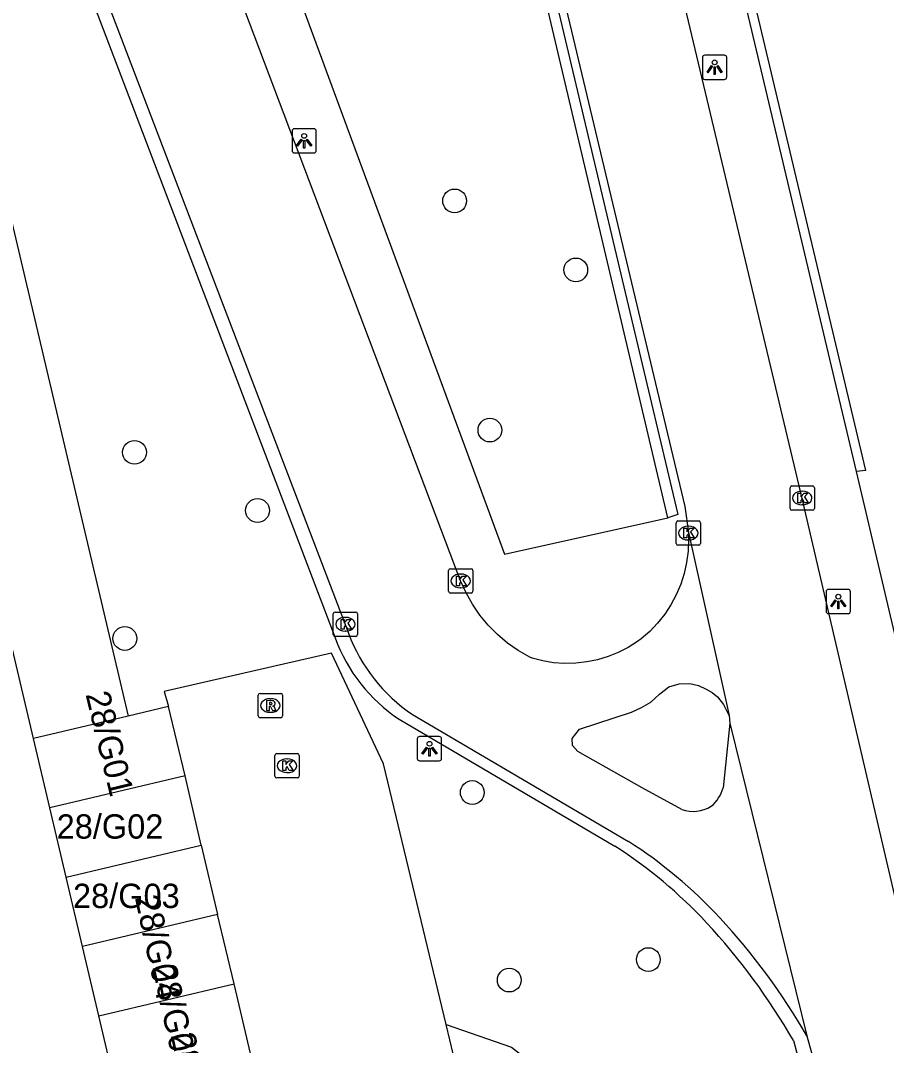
# Model space of a CAD drawing. Extents: x 158038 to 159242, y 380133 to 381214.
# Drawn here: x 158656.77 to 158692.37, y 380931.84 to 380973.99 of the extents above; entities that cross this region are included whole.
import ezdxf

# ---------------------------------------------------------------- set-up
doc = ezdxf.new("R2010")
doc.units = 0
for name, color, linetype in [('IMGEO_Boom', 7, 'Continuous'), ('IMGEO_Fietspad_open', 7, 'Continuous'), ('IMGEO_Groenvoorziening', 7, 'Continuous'), ('IMGEO_Kolk', 7, 'Continuous'), ('IMGEO_Lichtpunt', 7, 'Continuous'), ('IMGEO_Muur', 7, 'Continuous'), ('IMGEO_Pand', 7, 'Continuous'), ('IMGEO_Pand_nummerreeks', 7, 'Continuous'), ('IMGEO_Rijbaan_lokaal_open', 7, 'Continuous'), ('IMGEO_Rioolput', 7, 'Continuous'), ('IMGEO_Voetpad_open', 7, 'Continuous')]:
    doc.layers.add(name, color=color, linetype=linetype)

msp = doc.modelspace()

# ---------------------------------------------------------------- linework, layer by layer
at = {"layer": 'IMGEO_Boom'}
for centre in [(158674.616, 380966.569), (158679.594, 380963.733), (158676.065, 380957.145), (158661.456, 380956.231), (158666.512, 380953.838), (158661.059, 380948.576), (158675.342, 380942.239), (158682.578, 380935.369), (158676.862, 380934.526)]:
    msp.add_circle(centre, 0.489, dxfattribs=at)
at = {"layer": 'IMGEO_Fietspad_open'}
for points in [[(158709.619, 380866.64), (158709.463, 380867.521), (158707.319, 380876.312), (158699.376, 380909.991), (158693.603, 380934.169), (158688.921, 380954.272), (158678.032, 381000), (158677.125, 381004.39), (158673.033, 381021.228), (158672.927, 381021.669), (158667.035, 381046.28), (158663.617, 381061.042), (158663.576, 381061.221), (158663, 381063.616), (158656.793, 381089.506)], [(158672.361, 381001.891), (158674.016, 380996.666), (158679.129, 380974.762), (158684.079, 380953.998), (158684.223, 380952.937)], [(158652.006, 380996.675), (158660.379, 380974.663), (158670.252, 380948.792)], [(158684.223, 380952.937), (158684.233, 380952.634), (158684.213, 380952.167), (158684.152, 380951.704), (158684.049, 380951.249), (158683.907, 380950.804), (158683.725, 380950.374), (158683.505, 380949.962), (158683.25, 380949.572), (158682.961, 380949.205), (158682.64, 380948.866), (158682.29, 380948.557), (158682.134, 380948.445), (158681.749, 380948.204), (158681.344, 380947.999), (158680.922, 380947.831), (158680.487, 380947.701), (158680.043, 380947.61), (158679.591, 380947.56), (158679.138, 380947.55), (158678.685, 380947.58), (158678.236, 380947.651), (158677.796, 380947.762), (158677.702, 380947.81), (158677.233, 380948.079), (158676.791, 380948.389), (158676.379, 380948.738), (158675.999, 380949.122), (158675.655, 380949.538), (158675.349, 380949.983), (158675.084, 380950.454), (158674.863, 380950.947), (158665.761, 380975.033)], [(158684.223, 380952.937), (158685.897, 380945.401)], [(158683.953, 380941.54), (158682.328, 380942.428), (158679.675, 380943.932), (158679.46, 380944.173), (158679.44, 380944.458), (158679.75, 380944.851), (158681.884, 380945.55), (158682.291, 380945.731), (158682.676, 380945.956), (158683.036, 380946.283), (158683.42, 380946.582), (158683.846, 380946.711), (158684.29, 380946.727), (158684.636, 380946.643), (158684.959, 380946.494), (158685.202, 380946.352), (158685.418, 380946.171), (158685.664, 380945.862), (158685.84, 380945.508), (158685.897, 380945.401)], [(158672.883, 380945.448), (158681.756, 380940.231)], [(158685.897, 380945.401), (158685.924, 380945.089)], [(158685.924, 380945.089), (158685.65, 380942.439)], [(158685.924, 380945.089), (158689.094, 380932.233)], [(158689.094, 380932.233), (158689.866, 380929.463)]]:
    msp.add_lwpolyline(points, dxfattribs=at)
for centre, radius, start, end in [((158676.756, 380951.203), 6.937, 200.3348, 236.0552), ((158684.238, 380942.798), 1.457, 309.4682, 345.7445), ((158684.418, 380942.882), 1.42, 250.869, 301.6659), ((158671.318, 380923.935), 19.352, 42.7931, 57.3595), ((158666.009, 380918.956), 26.63, 29.9054, 42.8947)]:
    msp.add_arc(centre, radius, start, end, dxfattribs=at)
at = {"layer": 'IMGEO_Groenvoorziening'}
for points in [[(158649.276, 380995.98), (158661.198, 380945.385)], [(158657.305, 380944.468), (158645.377, 380995.088)], [(158674.266, 380932.695), (158676.956, 380931.767), (158679.919, 380929.472), (158680.934, 380926.931)]]:
    msp.add_lwpolyline(points, dxfattribs=at)
at = {"layer": 'IMGEO_Kolk'}
for p, q in [((158688.403, 380953.923), (158688.403, 380954.775)), ((158688.478, 380954.849), (158689.33, 380954.849)), ((158688.891, 380954.629), (158688.916, 380954.629)), ((158689.404, 380954.775), (158689.404, 380953.923)), ((158689.33, 380953.849), (158688.478, 380953.849)), ((158688.914, 380954.069), (158688.889, 380954.069)), ((158683.722, 380952.482), (158683.722, 380953.334)), ((158683.797, 380953.408), (158684.649, 380953.408)), ((158684.723, 380953.334), (158684.723, 380952.482)), ((158684.21, 380953.188), (158684.235, 380953.188)), ((158684.233, 380952.628), (158684.208, 380952.628)), ((158684.649, 380952.408), (158683.797, 380952.408)), ((158674.365, 380950.518), (158674.365, 380951.37)), ((158674.44, 380951.444), (158675.292, 380951.444)), ((158674.853, 380951.224), (158674.878, 380951.224)), ((158675.366, 380951.37), (158675.366, 380950.518)), ((158675.292, 380950.444), (158674.44, 380950.444)), ((158674.876, 380950.664), (158674.851, 380950.664)), ((158669.627, 380948.736), (158669.627, 380949.588)), ((158669.702, 380949.662), (158670.554, 380949.662)), ((158670.628, 380949.588), (158670.628, 380948.736)), ((158670.115, 380949.442), (158670.14, 380949.442)), ((158670.554, 380948.662), (158669.702, 380948.662)), ((158670.138, 380948.882), (158670.113, 380948.882)), ((158667.227, 380942.915), (158667.227, 380943.767)), ((158667.302, 380943.841), (158668.154, 380943.841)), ((158667.715, 380943.621), (158667.74, 380943.621)), ((158668.228, 380943.767), (158668.228, 380942.915)), ((158668.154, 380942.841), (158667.302, 380942.841)), ((158667.738, 380943.061), (158667.713, 380943.061))]:
    msp.add_line(p, q, dxfattribs=at)
for points in [[(158688.403, 380953.923), (158688.403, 380954.775)], [(158688.478, 380954.849), (158689.33, 380954.849)], [(158688.724, 380954.549), (158688.847, 380954.549), (158688.847, 380954.398), (158688.977, 380954.549), (158689.141, 380954.549), (158688.995, 380954.398), (158689.148, 380954.149), (158688.996, 380954.149), (158688.911, 380954.313), (158688.847, 380954.246), (158688.847, 380954.149), (158688.724, 380954.149), (158688.724, 380954.549)], [(158689.404, 380954.775), (158689.404, 380953.923)], [(158689.33, 380953.849), (158688.478, 380953.849)], [(158683.722, 380952.482), (158683.722, 380953.334)], [(158683.797, 380953.408), (158684.649, 380953.408)], [(158684.723, 380953.334), (158684.723, 380952.482)], [(158684.043, 380953.108), (158684.166, 380953.108), (158684.166, 380952.957), (158684.296, 380953.108), (158684.46, 380953.108), (158684.314, 380952.957), (158684.467, 380952.708), (158684.315, 380952.708), (158684.23, 380952.872), (158684.166, 380952.805), (158684.166, 380952.708), (158684.043, 380952.708), (158684.043, 380953.108)], [(158684.649, 380952.408), (158683.797, 380952.408)], [(158674.365, 380950.518), (158674.365, 380951.37)], [(158674.44, 380951.444), (158675.292, 380951.444)], [(158675.366, 380951.37), (158675.366, 380950.518)], [(158674.686, 380951.144), (158674.809, 380951.144), (158674.809, 380950.993), (158674.939, 380951.144), (158675.103, 380951.144), (158674.957, 380950.993), (158675.11, 380950.744), (158674.958, 380950.744), (158674.873, 380950.908), (158674.809, 380950.841), (158674.809, 380950.744), (158674.686, 380950.744), (158674.686, 380951.144)], [(158675.292, 380950.444), (158674.44, 380950.444)], [(158669.627, 380948.736), (158669.627, 380949.588)], [(158669.702, 380949.662), (158670.554, 380949.662)], [(158670.628, 380949.588), (158670.628, 380948.736)], [(158669.948, 380949.362), (158670.071, 380949.362), (158670.071, 380949.211), (158670.201, 380949.362), (158670.365, 380949.362), (158670.219, 380949.211), (158670.372, 380948.962), (158670.22, 380948.962), (158670.135, 380949.126), (158670.071, 380949.059), (158670.071, 380948.962), (158669.948, 380948.962), (158669.948, 380949.362)], [(158670.554, 380948.662), (158669.702, 380948.662)], [(158667.227, 380942.915), (158667.227, 380943.767)], [(158667.302, 380943.841), (158668.154, 380943.841)], [(158668.228, 380943.767), (158668.228, 380942.915)], [(158667.548, 380943.541), (158667.671, 380943.541), (158667.671, 380943.39), (158667.801, 380943.541), (158667.965, 380943.541), (158667.819, 380943.39), (158667.972, 380943.141), (158667.82, 380943.141), (158667.735, 380943.305), (158667.671, 380943.238), (158667.671, 380943.141), (158667.548, 380943.141), (158667.548, 380943.541)], [(158668.154, 380942.841), (158667.302, 380942.841)]]:
    msp.add_lwpolyline(points, dxfattribs=at)
for centre, start, end in [((158688.48, 380954.773), 91.552, 178.448), ((158688.48, 380954.773), 91.552, 178.448), ((158689.328, 380954.773), 1.552, 88.448), ((158689.328, 380954.773), 1.552, 88.448), ((158688.48, 380953.925), 181.552, 268.448), ((158688.48, 380953.925), 181.552, 268.448), ((158689.328, 380953.925), 271.552, 358.448), ((158689.328, 380953.925), 271.552, 358.448), ((158683.799, 380953.332), 91.552, 178.448), ((158683.799, 380953.332), 91.552, 178.448), ((158684.647, 380953.332), 1.552, 88.448), ((158684.647, 380953.332), 1.552, 88.448), ((158683.799, 380952.484), 181.552, 268.448), ((158683.799, 380952.484), 181.552, 268.448), ((158684.647, 380952.484), 271.552, 358.448), ((158684.647, 380952.484), 271.552, 358.448), ((158674.442, 380951.368), 91.552, 178.448), ((158674.442, 380951.368), 91.552, 178.448), ((158675.29, 380951.368), 1.552, 88.448), ((158675.29, 380951.368), 1.552, 88.448), ((158674.442, 380950.52), 181.552, 268.448), ((158674.442, 380950.52), 181.552, 268.448), ((158675.29, 380950.52), 271.552, 358.448), ((158675.29, 380950.52), 271.552, 358.448), ((158669.704, 380949.586), 91.552, 178.448), ((158669.704, 380949.586), 91.552, 178.448), ((158670.552, 380949.586), 1.552, 88.448), ((158670.552, 380949.586), 1.552, 88.448), ((158669.704, 380948.738), 181.552, 268.448), ((158669.704, 380948.738), 181.552, 268.448), ((158670.552, 380948.738), 271.552, 358.448), ((158670.552, 380948.738), 271.552, 358.448), ((158667.304, 380943.765), 91.552, 178.448), ((158667.304, 380943.765), 91.552, 178.448), ((158668.152, 380943.765), 1.552, 88.448), ((158668.152, 380943.765), 1.552, 88.448), ((158667.304, 380942.917), 181.552, 268.448), ((158667.304, 380942.917), 181.552, 268.448), ((158668.152, 380942.917), 271.552, 358.448), ((158668.152, 380942.917), 271.552, 358.448)]:
    msp.add_arc(centre, 0.0765, start, end, dxfattribs=at)
for centre, major_axis, ratio, start_param, end_param in [((158688.89, 380954.349), (-0.387, 0.002), 0.722429, 4.712389, 7.853982), ((158688.915, 380954.349), (-0.39, 0.002), 0.717154, 1.570796, 4.712389), ((158684.209, 380952.908), (-0.387, 0.002), 0.722429, 4.712389, 7.853982), ((158684.234, 380952.908), (-0.39, 0.002), 0.717154, 1.570796, 4.712389), ((158674.852, 380950.944), (-0.387, 0.002), 0.722429, 4.712389, 7.853982), ((158674.877, 380950.944), (-0.39, 0.002), 0.717154, 1.570796, 4.712389), ((158670.114, 380949.162), (-0.387, 0.002), 0.722429, 4.712389, 7.853982), ((158670.139, 380949.162), (-0.39, 0.002), 0.717154, 1.570796, 4.712389), ((158667.714, 380943.341), (-0.387, 0.002), 0.722429, 4.712389, 7.853982), ((158667.739, 380943.341), (-0.39, 0.002), 0.717154, 1.570796, 4.712389)]:
    msp.add_ellipse(centre, major_axis=major_axis, ratio=ratio, start_param=start_param, end_param=end_param, dxfattribs=at)
at = {"layer": 'IMGEO_Lichtpunt'}
for p, q in [((158684.804, 380972.469), (158684.804, 380971.662)), ((158684.804, 380972.469), (158684.804, 380971.662)), ((158685.706, 380972.564), (158684.898, 380972.564)), ((158685.706, 380972.564), (158684.898, 380972.564)), ((158685.8, 380971.662), (158685.8, 380972.469)), ((158685.8, 380971.662), (158685.8, 380972.469)), ((158684.898, 380971.568), (158685.706, 380971.568)), ((158684.898, 380971.568), (158685.706, 380971.568)), ((158667.933, 380969.445), (158667.933, 380968.638)), ((158667.933, 380969.445), (158667.933, 380968.638)), ((158668.835, 380969.54), (158668.027, 380969.54)), ((158668.835, 380969.54), (158668.027, 380969.54)), ((158668.929, 380968.638), (158668.929, 380969.445)), ((158668.929, 380968.638), (158668.929, 380969.445)), ((158668.027, 380968.544), (158668.835, 380968.544)), ((158668.027, 380968.544), (158668.835, 380968.544)), ((158689.887, 380950.497), (158689.887, 380949.69)), ((158689.887, 380950.497), (158689.887, 380949.69)), ((158690.789, 380950.592), (158689.981, 380950.592)), ((158690.789, 380950.592), (158689.981, 380950.592)), ((158690.883, 380949.69), (158690.883, 380950.497)), ((158690.883, 380949.69), (158690.883, 380950.497)), ((158689.981, 380949.596), (158690.789, 380949.596)), ((158689.981, 380949.596), (158690.789, 380949.596)), ((158673.082, 380944.448), (158673.082, 380943.641)), ((158673.082, 380944.448), (158673.082, 380943.641)), ((158673.984, 380944.543), (158673.176, 380944.543)), ((158673.984, 380944.543), (158673.176, 380944.543)), ((158674.078, 380943.641), (158674.078, 380944.448)), ((158674.078, 380943.641), (158674.078, 380944.448)), ((158673.176, 380943.547), (158673.984, 380943.547)), ((158673.176, 380943.547), (158673.984, 380943.547))]:
    msp.add_line(p, q, dxfattribs=at)
for points in [[(158685.178, 380972.133), (158685.217, 380972.105), (158685.029, 380971.843), (158684.991, 380971.87), (158685.178, 380972.133)], [(158685.28, 380972.085), (158685.327, 380972.085), (158685.327, 380971.763), (158685.28, 380971.763), (158685.28, 380972.085)], [(158685.39, 380972.105), (158685.428, 380972.132), (158685.615, 380971.87), (158685.576, 380971.842), (158685.39, 380972.105)], [(158668.307, 380969.109), (158668.346, 380969.081), (158668.158, 380968.819), (158668.12, 380968.846), (158668.307, 380969.109)], [(158668.409, 380969.061), (158668.456, 380969.061), (158668.456, 380968.739), (158668.409, 380968.739), (158668.409, 380969.061)], [(158668.519, 380969.081), (158668.557, 380969.108), (158668.744, 380968.846), (158668.705, 380968.818), (158668.519, 380969.081)], [(158690.261, 380950.161), (158690.3, 380950.133), (158690.112, 380949.871), (158690.074, 380949.898), (158690.261, 380950.161)], [(158690.363, 380950.113), (158690.41, 380950.113), (158690.41, 380949.791), (158690.363, 380949.791), (158690.363, 380950.113)], [(158690.473, 380950.133), (158690.511, 380950.16), (158690.698, 380949.898), (158690.659, 380949.87), (158690.473, 380950.133)], [(158673.456, 380944.112), (158673.495, 380944.084), (158673.307, 380943.822), (158673.269, 380943.849), (158673.456, 380944.112)], [(158673.558, 380944.064), (158673.605, 380944.064), (158673.605, 380943.742), (158673.558, 380943.742), (158673.558, 380944.064)], [(158673.668, 380944.084), (158673.706, 380944.111), (158673.893, 380943.849), (158673.854, 380943.821), (158673.668, 380944.084)]]:
    msp.add_lwpolyline(points, dxfattribs=at)
for centre in [(158685.303, 380972.267), (158668.432, 380969.243), (158690.386, 380950.295), (158673.581, 380944.246)]:
    msp.add_circle(centre, 0.0994, dxfattribs=at)
for centre, start, end in [((158684.898, 380972.469), 90, 180), ((158684.898, 380972.469), 90, 180), ((158685.706, 380972.469), 0, 90), ((158685.706, 380972.469), 0, 90), ((158684.898, 380971.662), 180, 270), ((158684.898, 380971.662), 180, 270), ((158685.706, 380971.662), 270, 0), ((158685.706, 380971.662), 270, 360), ((158668.027, 380969.445), 90, 180), ((158668.027, 380969.445), 90, 180), ((158668.835, 380969.445), 0, 90), ((158668.835, 380969.445), 0, 90), ((158668.027, 380968.638), 180, 270), ((158668.027, 380968.638), 180, 270), ((158668.835, 380968.638), 270, 0), ((158668.835, 380968.638), 270, 360), ((158689.981, 380950.497), 90, 180), ((158689.981, 380950.497), 90, 180), ((158690.789, 380950.497), 0, 90), ((158690.789, 380950.497), 0, 90), ((158689.981, 380949.69), 180, 270), ((158689.981, 380949.69), 180, 270), ((158690.789, 380949.69), 270, 0), ((158690.789, 380949.69), 270, 360), ((158673.176, 380944.448), 90, 180), ((158673.176, 380944.448), 90, 180), ((158673.984, 380944.448), 0, 90), ((158673.984, 380944.448), 0, 90), ((158673.176, 380943.641), 180, 270), ((158673.176, 380943.641), 180, 270), ((158673.984, 380943.641), 270, 0), ((158673.984, 380943.641), 270, 360)]:
    msp.add_arc(centre, 0.0946, start, end, dxfattribs=at)
at = {"layer": 'IMGEO_Muur'}
for points in [[(158683.376, 380953.532), (158671.995, 381001.81)], [(158672.361, 381001.891), (158683.797, 380953.67), (158683.376, 380953.532)], [(158691.138, 380955.441), (158680.141, 381001.782)], [(158680.496, 381001.857), (158691.506, 380955.478), (158691.138, 380955.441)]]:
    msp.add_lwpolyline(points, dxfattribs=at)
at = {"layer": 'IMGEO_Pand'}
for points in [[(158662.86, 380945.776), (158661.198, 380945.385)], [(158663.532, 380942.924), (158662.86, 380945.776)], [(158661.198, 380945.385), (158657.305, 380944.468)], [(158657.976, 380941.616), (158657.305, 380944.468)], [(158663.532, 380942.924), (158657.976, 380941.616)], [(158664.203, 380940.071), (158663.532, 380942.924)], [(158658.648, 380938.763), (158657.976, 380941.616)], [(158658.648, 380938.763), (158664.203, 380940.071)], [(158664.203, 380940.071), (158664.874, 380937.218)], [(158659.32, 380935.911), (158658.648, 380938.763)], [(158664.874, 380937.218), (158659.32, 380935.911)], [(158665.546, 380934.366), (158664.874, 380937.218)], [(158659.991, 380933.058), (158659.32, 380935.911)], [(158659.991, 380933.058), (158665.546, 380934.366)], [(158666.218, 380931.513), (158665.546, 380934.366)], [(158660.663, 380930.206), (158659.991, 380933.058)]]:
    msp.add_lwpolyline(points, dxfattribs=at)
at = {"layer": 'IMGEO_Rijbaan_lokaal_open'}
for points in [[(158674.266, 380932.695), (158671.693, 380943.415), (158669.548, 380947.966), (158662.669, 380946.393), (158662.86, 380945.776)], [(158675.929, 380925.769), (158674.266, 380932.695)]]:
    msp.add_lwpolyline(points, dxfattribs=at)
at = {"layer": 'IMGEO_Rioolput'}
for p, q in [((158666.541, 380945.392), (158666.541, 380946.244)), ((158666.616, 380946.318), (158667.468, 380946.318)), ((158667.542, 380946.244), (158667.542, 380945.392)), ((158667.029, 380946.098), (158667.054, 380946.098)), ((158667.468, 380945.318), (158666.616, 380945.318)), ((158667.052, 380945.538), (158667.027, 380945.538))]:
    msp.add_line(p, q, dxfattribs=at)
for points in [[(158666.541, 380945.392), (158666.541, 380946.244)], [(158666.616, 380946.318), (158667.468, 380946.318)], [(158667.542, 380946.244), (158667.542, 380945.392)], [(158667.13, 380946.016), (158666.878, 380946.018), (158666.878, 380945.618)], [(158666.878, 380945.618), (158667.002, 380945.618), (158667.002, 380945.78), (158667.013, 380945.78)], [(158667.056, 380945.937), (158667.002, 380945.937), (158667.002, 380945.856)], [(158667.002, 380945.856), (158667.054, 380945.856)], [(158667.06, 380945.751), (158667.131, 380945.618), (158667.271, 380945.618), (158667.206, 380945.744)], [(158667.468, 380945.318), (158666.616, 380945.318)]]:
    msp.add_lwpolyline(points, dxfattribs=at)
for centre, radius, start, end in [((158666.618, 380946.242), 0.0765, 91.552, 178.448), ((158666.618, 380946.242), 0.0765, 91.552, 178.448), ((158667.466, 380946.242), 0.0765, 1.552, 88.448), ((158667.466, 380946.242), 0.0765, 1.552, 88.448), ((158667.012, 380945.727), 0.0533, 26.0293, 88.6989), ((158667.038, 380946.045), 0.19, 274.7715, 282.9687), ((158667.062, 380945.841), 0.0964, 77.0061, 93.1865), ((158667.076, 380945.898), 0.0378, 276.6634, 79.6772), ((158667.129, 380945.906), 0.109, 350.3612, 89.416), ((158667.127, 380945.906), 0.112, 277.5842, 350.9817), ((158667.111, 380945.691), 0.108, 29.5134, 73.7905), ((158666.618, 380945.394), 0.0765, 181.552, 268.448), ((158666.618, 380945.394), 0.0765, 181.552, 268.448), ((158667.466, 380945.394), 0.0765, 271.552, 358.448), ((158667.466, 380945.394), 0.0765, 271.552, 358.448)]:
    msp.add_arc(centre, radius, start, end, dxfattribs=at)
for centre, major_axis, ratio, start_param, end_param in [((158667.028, 380945.818), (-0.387, 0.002), 0.722429, 4.712389, 7.853982), ((158667.053, 380945.818), (-0.39, 0.002), 0.717154, 1.570796, 4.712389)]:
    msp.add_ellipse(centre, major_axis=major_axis, ratio=ratio, start_param=start_param, end_param=end_param, dxfattribs=at)
at = {"layer": 'IMGEO_Voetpad_open'}
for points in [[(158659.843, 380997.893), (158660.03, 380997.272), (158666.732, 380978.988), (158676.668, 380952.037), (158683.376, 380953.532)], [(158651.455, 380996.478), (158669.701, 380948.595)], [(158710.56, 380872.948), (158691.138, 380955.441)], [(158672.332, 380945.251), (158681.205, 380940.034)], [(158688.543, 380932.036), (158689.258, 380929.353)]]:
    msp.add_lwpolyline(points, dxfattribs=at)
for centre, radius, start, end in [((158676.205, 380951.006), 6.937, 200.3348, 236.0552), ((158670.767, 380923.738), 19.352, 42.7931, 57.3595), ((158665.458, 380918.759), 26.63, 29.9054, 42.8947)]:
    msp.add_arc(centre, radius, start, end, dxfattribs=at)

# ---------------------------------------------------------------- texts
at = {"layer": 'IMGEO_Pand_nummerreeks'}
for s, rotation, p in [('28/G01', 283.5704, (158659.439, 380946.279)), ('28/G04', 282.1886, (158661.469, 380937.917)), ('28/G05', 282.1886, (158662.182, 380935.064)), ('28/G06', 282.1886, (158662.941, 380932.258))]:
    msp.add_text(s, height=1, rotation=rotation, dxfattribs=at).set_placement(p)
for s, p in [('28/G02', (158658.256, 380940.344)), ('28/G03', (158658.928, 380937.491))]:
    msp.add_text(s, height=1, dxfattribs=at).set_placement(p)

doc.saveas('drawing.dxf')
